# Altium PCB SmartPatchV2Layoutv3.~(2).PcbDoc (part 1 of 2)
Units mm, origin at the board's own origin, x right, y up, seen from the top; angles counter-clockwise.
Board outline 99.82 x 98.31 mm, 4 copper layers (Top Layer, Power, GroundPlane, Bottom Layer), stack 2.286 mm thick; 142 components, 77 nets, 387 pads, 123 vias.
Unrouted connection lines stored in the file: 2.
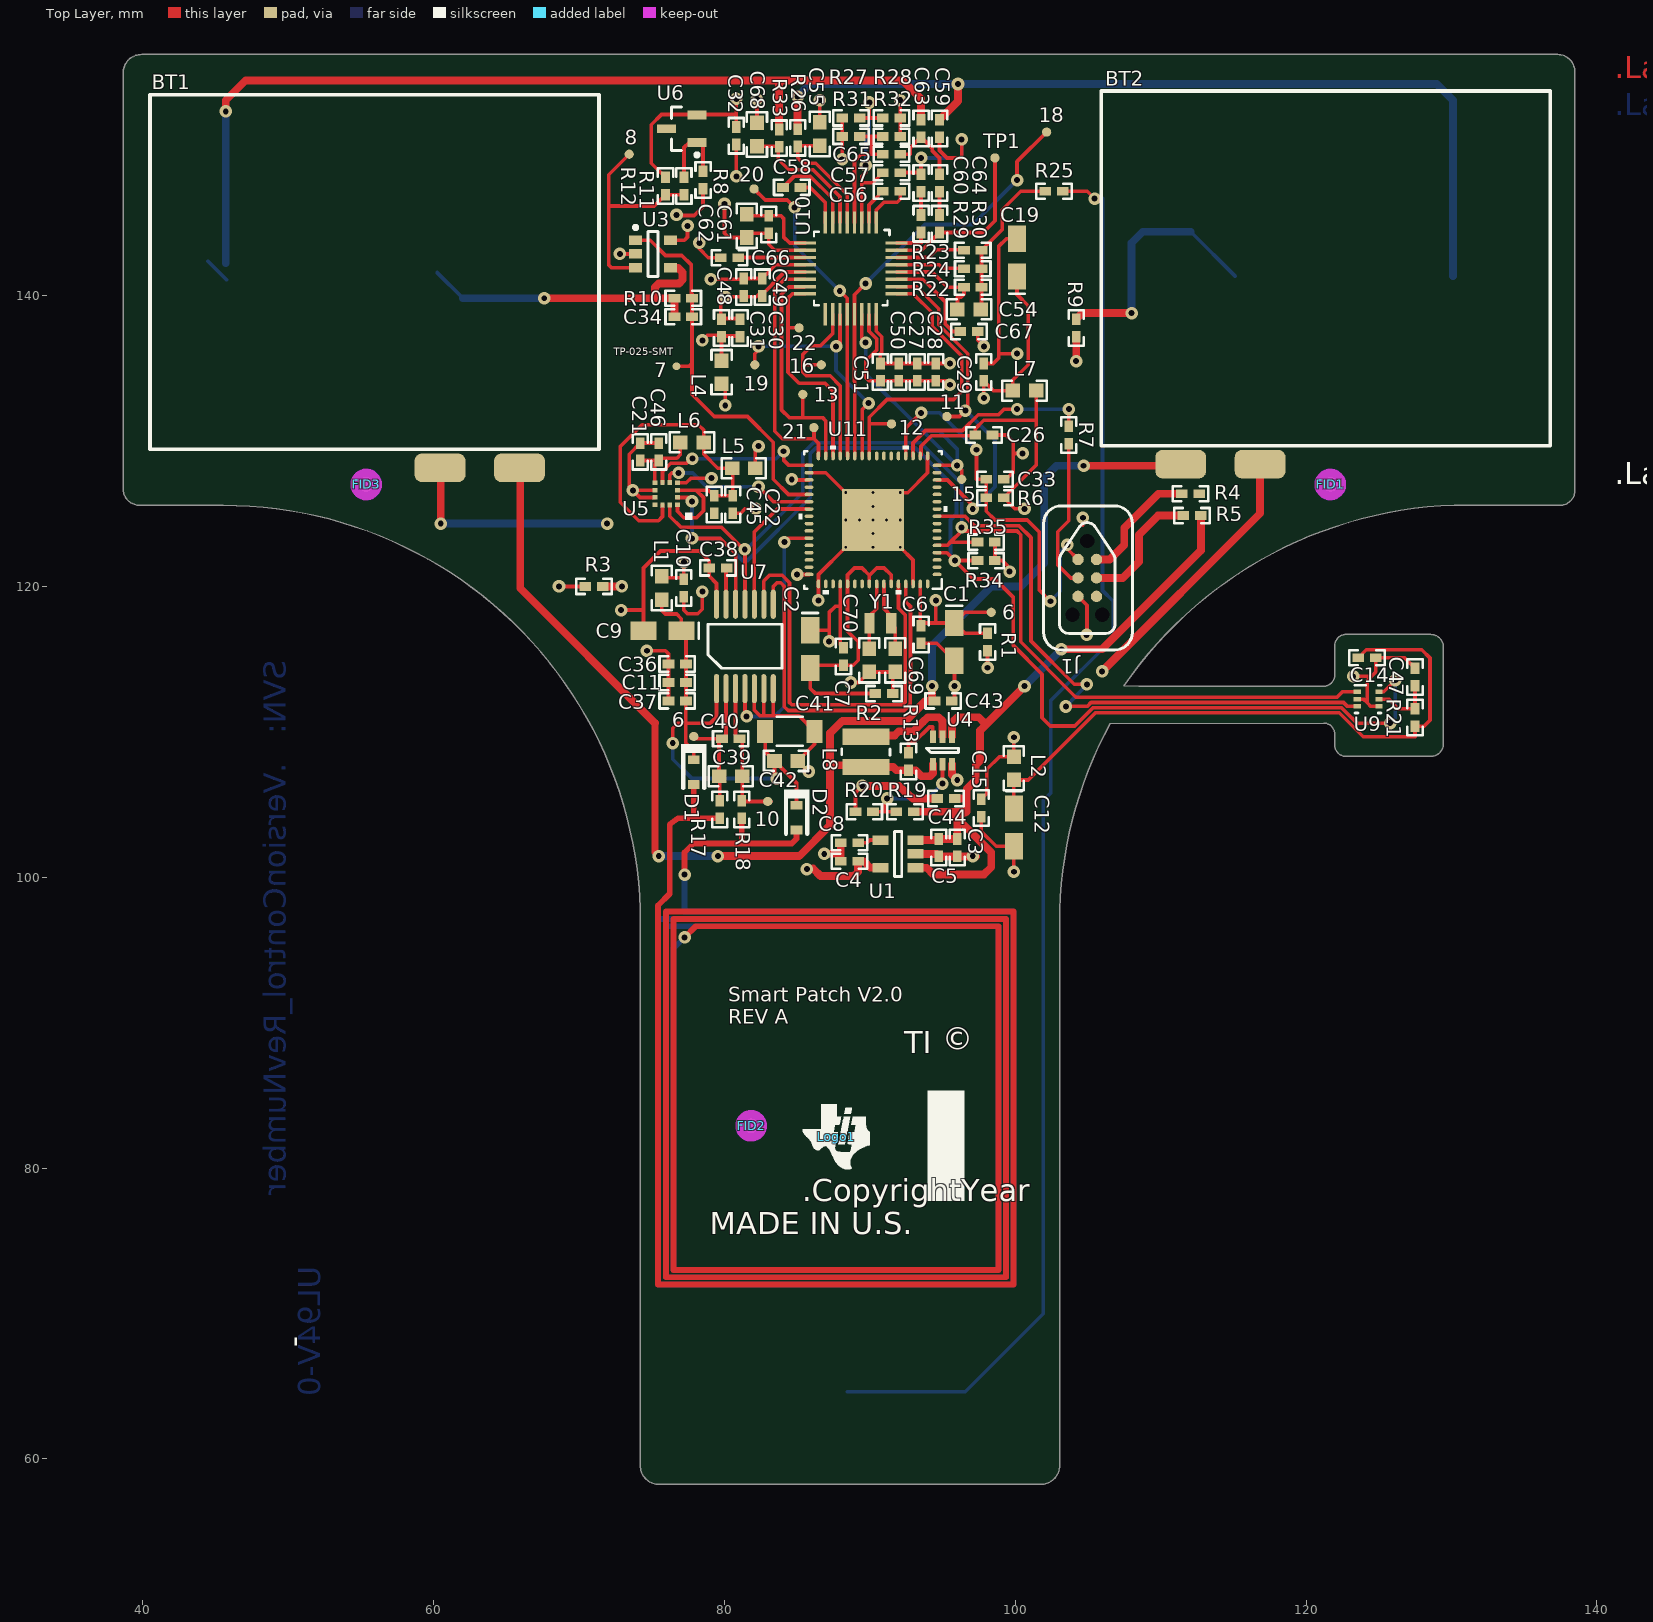
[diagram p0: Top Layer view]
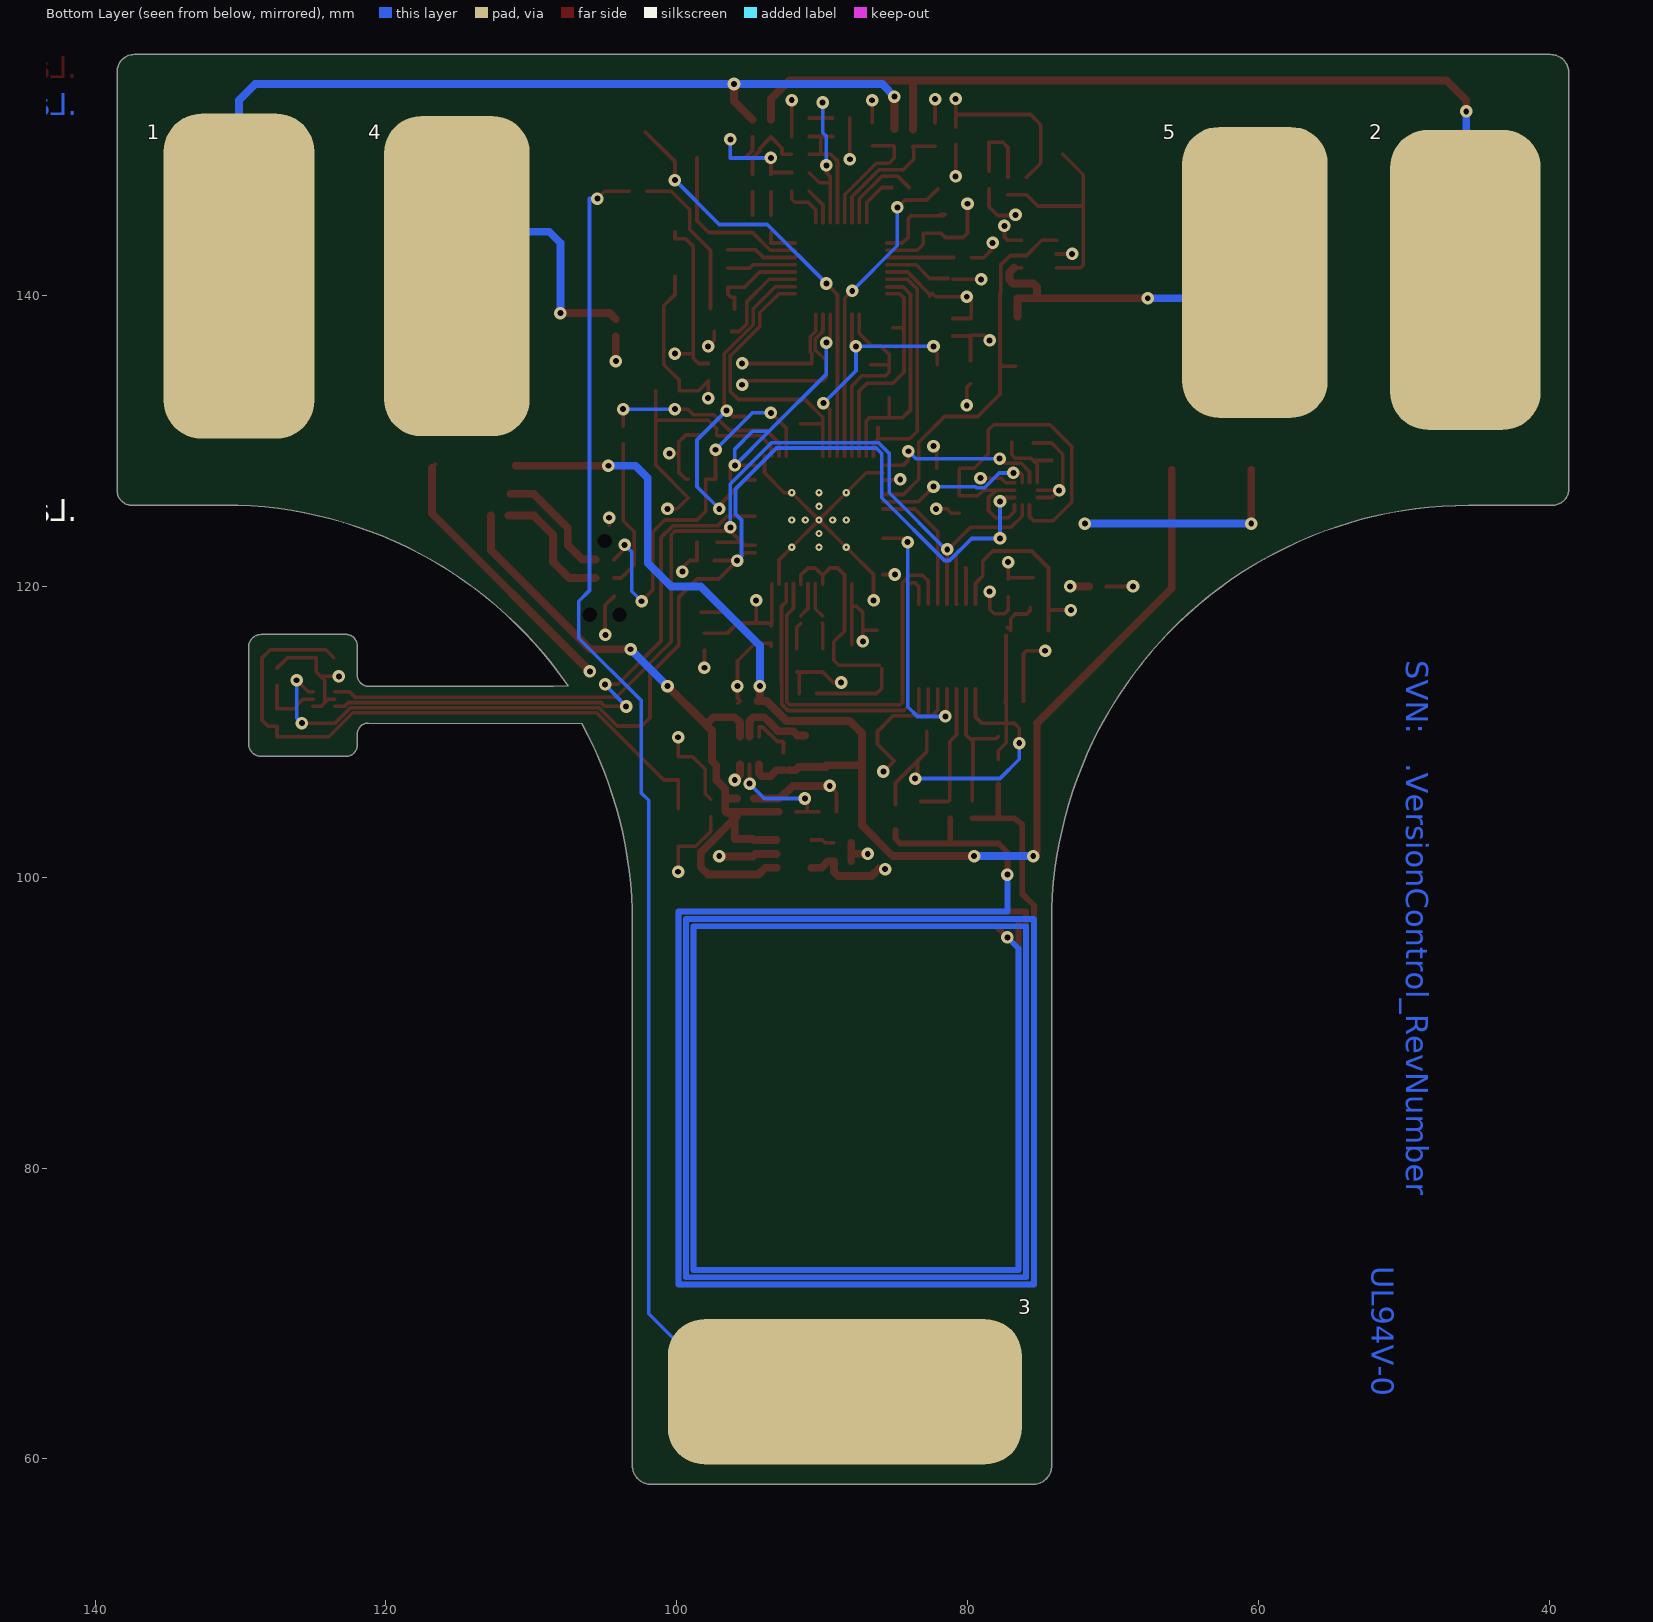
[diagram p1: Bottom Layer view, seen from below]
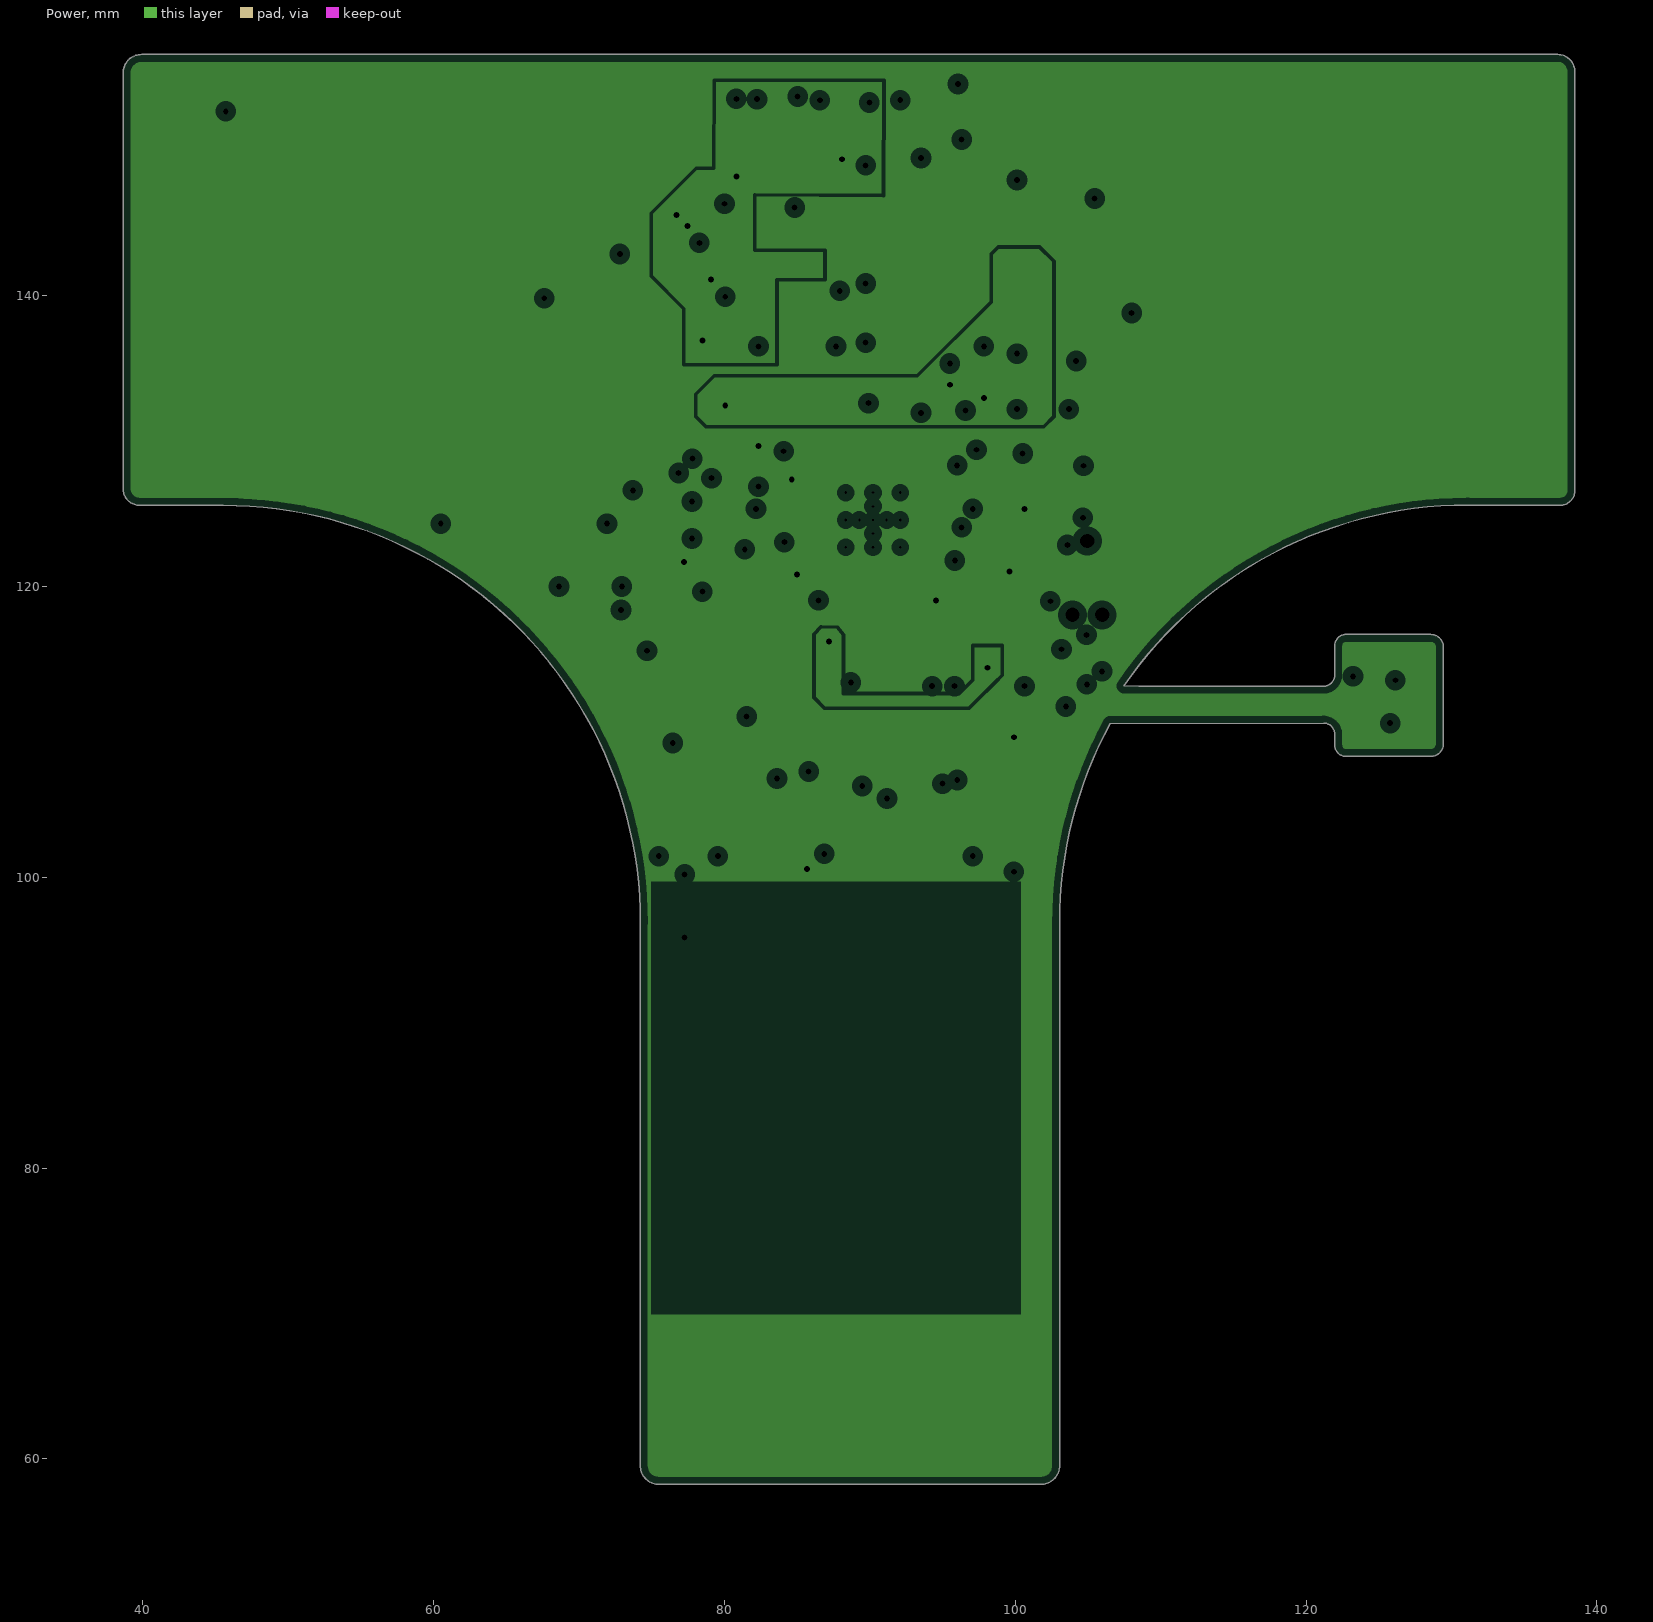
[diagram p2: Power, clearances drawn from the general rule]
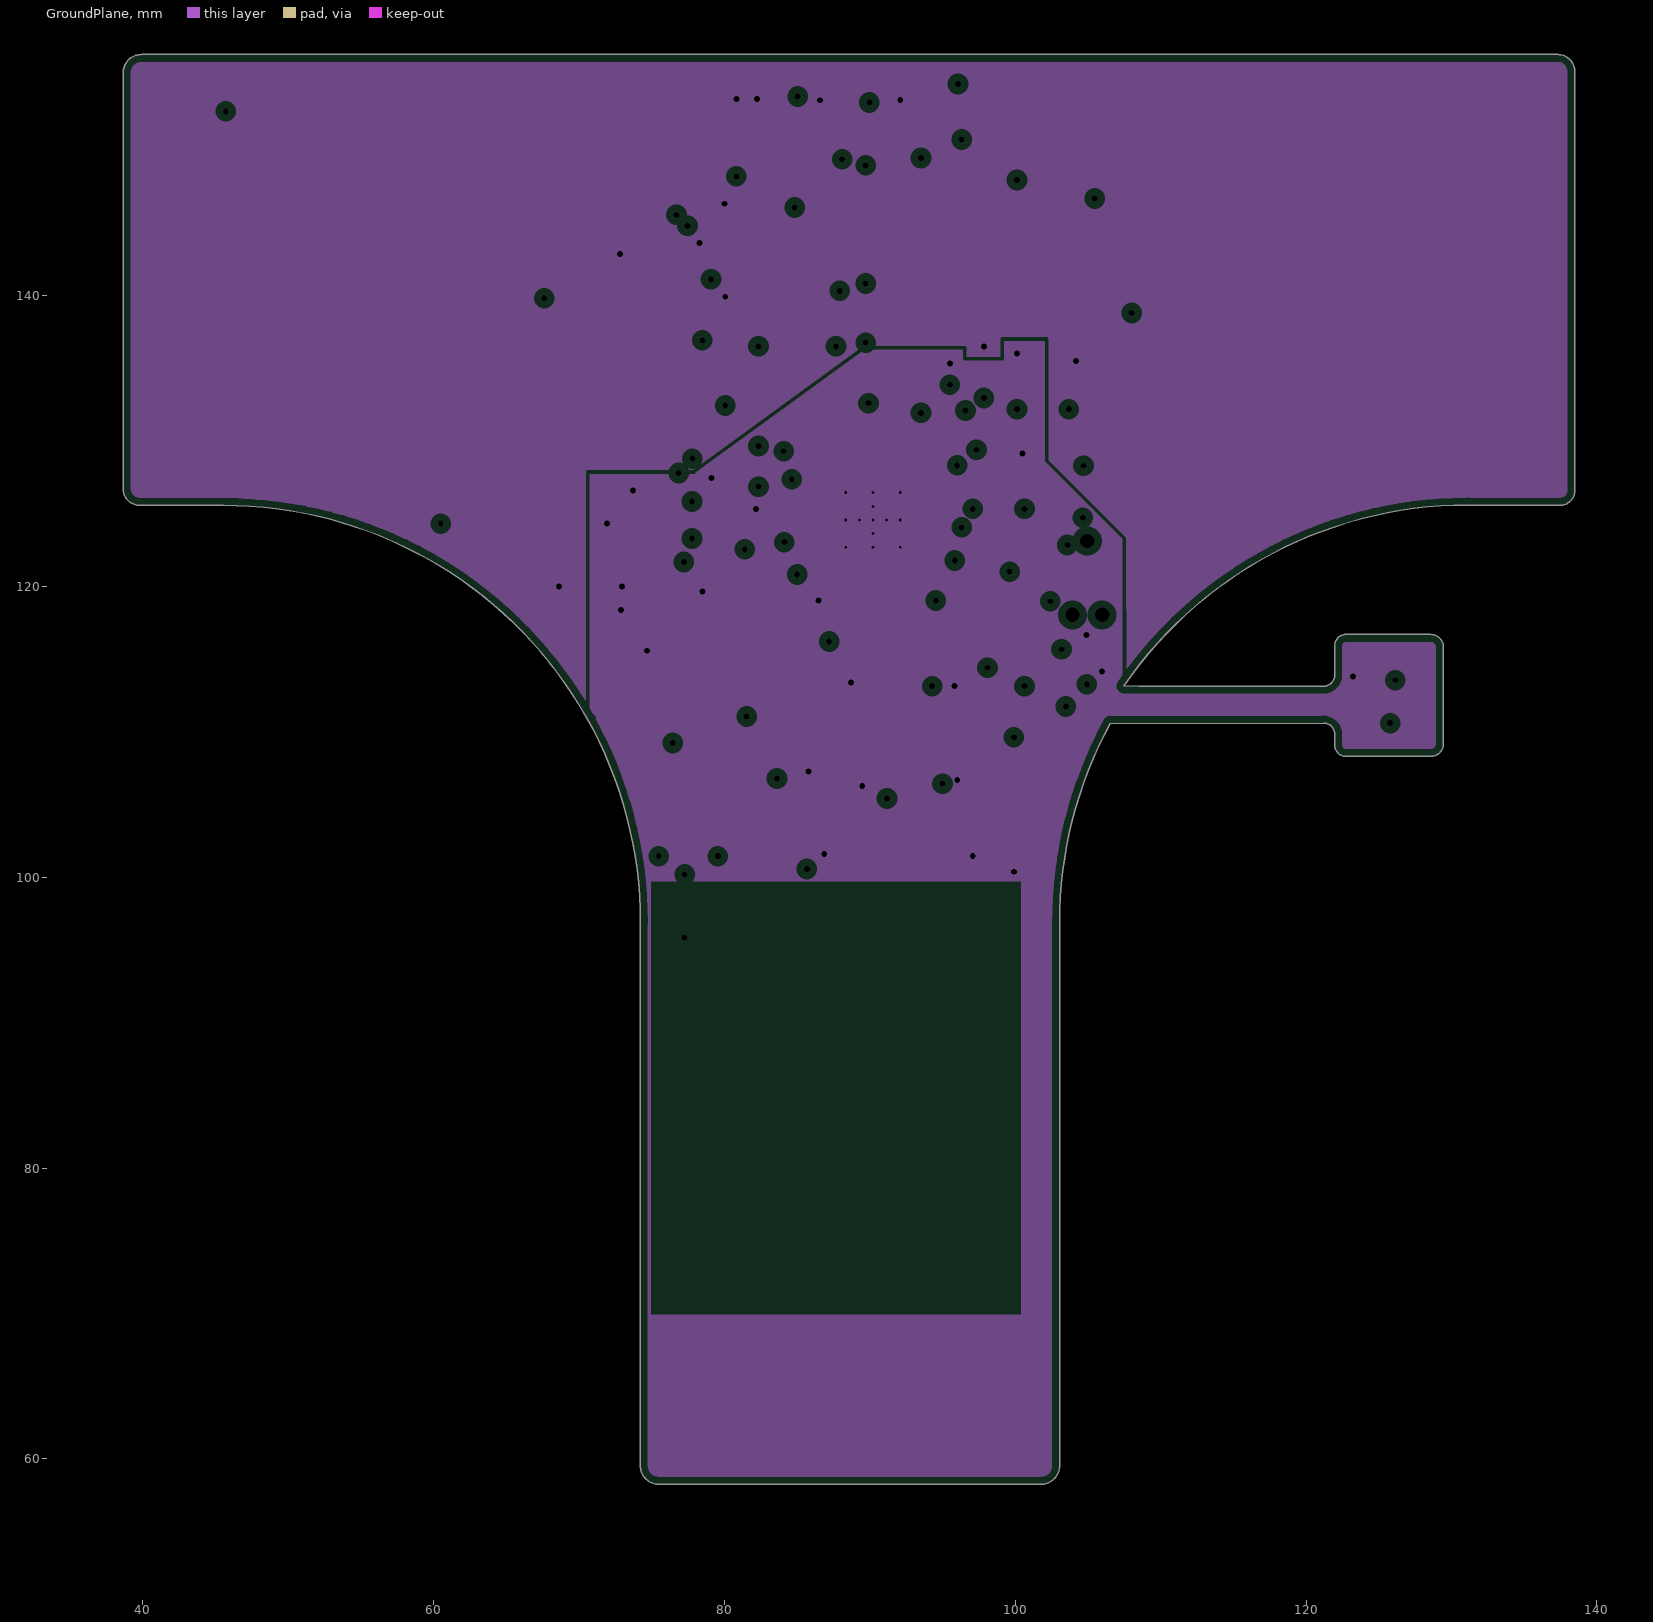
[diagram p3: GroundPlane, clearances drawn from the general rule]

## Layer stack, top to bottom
Top Layer: signal copper 0.0356
Dielectric: core 1.5037, FR-4, Dk 4.8
Power: plane copper 0.0356, net (Multiple Nets)
Dielectric: prepreg 0.32, FR-4, Dk 4.8
GroundPlane: plane copper 0.0356, net (Multiple Nets)
Dielectric: core 0.32, FR-4, Dk 4.8
Bottom Layer: signal copper 0.0356

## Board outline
74.219,59.527 ccw(c75.489,59.527) 75.489,58.257 101.778,58.257 ccw(c101.778,59.527) 103.048,59.527 103.048,96.875 cw(c131.74,96.875) 106.525,110.565 121.209,110.592 cw(c121.209,109.83) 121.971,109.83 121.971,109.068 ccw(c122.733,109.068) 122.733,108.306 128.575,108.306 ccw(c128.575,109.173) 129.442,109.173 129.442,115.82 ccw(c128.575,115.82) 128.575,116.688 122.733,116.688 ccw(c122.733,115.926) 121.971,115.926 121.971,113.894 cw(c121.209,113.894) 121.209,113.132 108.509,113.132 107.469,113.147 cw(c131.115,96.896) 131.115,125.588 132.639,125.576 137.454,125.567 ccw(c137.454,126.594) 138.481,126.594 138.481,155.379 ccw(c137.294,155.379) 137.294,156.566 39.929,156.566 ccw(c39.929,155.296) 38.659,155.296 38.659,126.714 38.657,126.714 ccw(c39.804,126.714) 39.804,125.568 45.537,125.568 cw(c45.537,96.876) 74.229,96.876 74.219,96.875

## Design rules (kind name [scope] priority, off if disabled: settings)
AcuteAngle [All] p1: minimum=4.50000000000000E+0001 checktracksonly=FALSE
AssemblyTestPointUsage [All] p1: valid=2
Clearance Clearance_BoardEdge_MountingHoles [OnCopper and InComponentClass('Mounting Holes') vs IsKeepOut] p1: gap=1.016
Clearance Clearance_BoardEdge_Poly [OnCopper and InPoly vs IsKeepOut] p2: gap=0.635
Clearance Clearance_BoardEdge [OnCopper and Not InComponentClass('Logo') and not InComponentClass('FiducialMark') and not InRegion(1000,500,4000,800) and Not IsKeepout vs IsKeepOut] p3: gap=1.905
Clearance Clearance_Poly [InPolygon] p4: gap=0.635
Clearance [All] p5: gap=0.1
ComponentClearance ComponentClearance_Shunt [InComponentClass('Header') vs InComponentClass('Shunt')] p1: gap=0 collisioncheckmode=3 verticalgap=0 showdistances=FALSE
ComponentClearance ComponentClearance_MountingHoles_FiducialMarks [InComponentClass('Mounting Holes') vs InComponentClass('FiducialMark')] p2: gap=1.27 collisioncheckmode=3 verticalgap=0.254 showdistances=FALSE
ComponentClearance ComponentClearance_Logo [InComponentClass('Logo')] p3: gap=1.27 collisioncheckmode=3 verticalgap=0.254 showdistances=FALSE
ComponentClearance ComponentClearance_ScrewToNut [(HasFootprint('NY PMS 440 0025 PH')) vs (HasFootprint('Keystone_1902C'))] p4: gap=0.127 collisioncheckmode=3 verticalgap=0.254 showdistances=FALSE
ComponentClearance ComponentClearance_MountingHoles [InComponentClass('Mounting Holes')] p5: gap=6.35 collisioncheckmode=3 verticalgap=2540 showdistances=FALSE
ComponentClearance ComponentClearance_SmallPassives [HasFootprint('0201*') or HasFootprint('0402*') or HasFootprint('0508') or HasFootprint('0603*') or HasFootprint('0612') or HasFootprint('0805*') or HasFootprint('0815*') or HasFootprint('0830*') or HasFootprint('1206*') or HasFootprint('1210*') or HasFootprint('1808*') or HasFootprint('1812*') or HasFootprint('1825*') or HasFootprint('2010*') or HasFootprint('2220*') or HasFootprint('2225*') or HasFootprint('2512*') or HasFootprint('2728*') or HasFootprint('3518*') vs HasFootprint('0201*') or HasFootprint('0402*') or HasFootprint('0508') or HasFootprint('0603*') or HasFootprint('0612') or HasFootprint('0805*') or HasFootprint('0815*') or HasFootprint('0830*') or HasFootprint('1206*') or HasFootprint('1210*') or HasFootprint('1808*') or HasFootprint('1812*') or HasFootprint('1825*') or HasFootprint('2010*') or HasFootprint('2220*') or HasFootprint('2225*') or HasFootprint('2512*') or HasFootprint('2728*') or HasFootprint('3518*')] p6: gap=0.508 collisioncheckmode=3 verticalgap=0.254 showdistances=FALSE
ComponentClearance ComponentClearance_THtoSMT [IsThruComponent vs IsSMTComponent] p7: gap=2.54 collisioncheckmode=3 verticalgap=0.762 showdistances=FALSE
ComponentClearance ComponentClearance_THtoTH [IsThruComponent vs IsThruComponent] p8: gap=3 collisioncheckmode=3 verticalgap=0.762 showdistances=FALSE
ComponentClearance [All] p9: gap=1.016 collisioncheckmode=3 verticalgap=0.254 showdistances=FALSE
DiffPairsRouting [All] p1: maxlimit=2.54 minlimit=0.254 mostfreqgap=0.254 maxuncoupledlength=25.4
FabricationTestPointUsage TestPointUsage [All] p1: valid=2 allowmultiple=FALSE
FabricationTestpoint Testpoint [All] p1: side=3 testpointundercomponent=TRUE minsize=1.016 maxsize=2.54 preferedsize=1.524 minholesize=0 maxholesize=1.016 preferedholesize=0.813 testpointgrid=0.025 allowsidetop=TRUE allowsidebottom=TRUE usegrid=TRUE gridtolerance=0
FanoutControl Fanout_LCC [IsLCC] p1: bgadir=Out bgaviamode=Centered fanoutstyle=Auto fanoutdirection=Alternating viagrid=0.025 // Fanout_LCC (Default Rule)
FanoutControl Fanout_BGA [IsBGA] p2: bgadir=Out bgaviamode=Centered fanoutstyle=Auto fanoutdirection=Alternating viagrid=0.025 // Fanout_BGA (Default Rule)
FanoutControl Fanout_Default [All] p4: bgadir=Out bgaviamode=Centered fanoutstyle=Auto fanoutdirection=Alternating viagrid=0.025 // Fanout_Default (Default Rule)
FanoutControl Fanout_Small [(CompPinCount < 5)] p5: bgadir=Out bgaviamode=Centered fanoutstyle=Auto fanoutdirection=OutThenIn viagrid=0.025 // Fanout_Small (Default Rule)
Height [All] p1: minheight=0 maxheight=55.4 prefheight=12.7
HoleSize [All] p1: absolutevalues=TRUE maxlimit=6.375 minlimit=0.1 maxpercent=80.000 minpercent=20.000
MinimumAnnularRing MinimumAnnularRing_ThermalPadVias [IsVia and InAnyComponent] p1: minimumring=0.15
MinimumAnnularRing [All] p2: minimumring=0.229
MinimumSolderMaskSliver MinimumSolderMaskSliver_Logo [InComponentClass('Logo') vs InComponentClass('Logo')] p1: minsoldermaskwidth=0.018
MinimumSolderMaskSliver [All] p2: minsoldermaskwidth=0.08
PlaneClearance [All] p1: clearance=0.508
PlaneConnect [All] p1: planeconnectstyle=Relief reliefexpansion=0.254 reliefentries=4 reliefconductorwidth=0.254 reliefairgap=0.254
PolygonConnect [All] p1: connectstyle=Relief reliefconductorwidth=0.254 reliefentries=4 polygonreliefangle="90 Angle" airgapwidth=0.254
RoomDefinition Transponder [InComponentClass('Transponder')] p1: confinementstyle=ConfineIn formatcopy=TRUE lockcomponents=FALSE outline 0,0 50.8,0 50.8,25.4 0,25.4
RoomDefinition Temperature [InComponentClass('Temperature')] p2: confinementstyle=ConfineIn formatcopy=TRUE lockcomponents=FALSE outline 0,0 50.8,0 50.8,25.4 0,25.4
RoomDefinition MSP430FR5XXX [InComponentClass('MSP430FR5XXX')] p3: confinementstyle=ConfineIn formatcopy=TRUE lockcomponents=FALSE outline 0,0 50.8,0 50.8,25.4 0,25.4
RoomDefinition "JTAG SPY-BY-WIRE" [InComponentClass('JTAG SPY-BY-WIRE')] p4: confinementstyle=ConfineIn formatcopy=TRUE lockcomponents=FALSE outline 0,0 50.8,0 50.8,25.4 0,25.4
RoomDefinition GSR [InComponentClass('GSR')] p5: confinementstyle=ConfineIn formatcopy=TRUE lockcomponents=FALSE outline 0,0 50.8,0 50.8,25.4 0,25.4
RoomDefinition ECG [InComponentClass('ECG')] p6: confinementstyle=ConfineIn formatcopy=TRUE lockcomponents=FALSE outline 0,0 50.8,0 50.8,25.4 0,25.4
RoomDefinition "Boost Converter" [InComponentClass('Boost Converter')] p7: confinementstyle=ConfineIn formatcopy=TRUE lockcomponents=FALSE outline 0,0 50.8,0 50.8,25.4 0,25.4
RoomDefinition BMA280 [InComponentClass('BMA280')] p8: confinementstyle=ConfineIn formatcopy=TRUE lockcomponents=FALSE outline 0,0 50.8,0 50.8,25.4 0,25.4
RoomDefinition Battery [InComponentClass('Battery')] p9: confinementstyle=ConfineIn formatcopy=TRUE lockcomponents=FALSE outline 0,0 50.8,0 50.8,25.4 0,25.4
RoutingVias ThermalPadVias [IsVia and InAnyComponent] p1: holewidth=0.2 width=0.5 viastyle="Through Hole" minholewidth=0.2 minwidth=0.5 maxholewidth=0.33 maxwidth=0.6
RoutingVias [All] p2: holewidth=0.406 width=0.864 viastyle="Through Hole" minholewidth=0.2 minwidth=0.66 maxholewidth=1.016 maxwidth=1.651
SMDToCorner [All] p1: distance=30000
SilkToSilkClearance SilkToSilkClearance_Pb-FreeLogo [(HasFootprint('Pb-Free_Overlay_Medium') OR HasFootprint('Pb-Free_Overlay_Small')) vs (HasFootprint('Pb-Free_Overlay_Medium') OR HasFootprint('Pb-Free_Overlay_Small'))] p1: silktosilkclearance=0
SilkToSilkClearance [All] p2: silktosilkclearance=0
SilkscreenOverComponentPads [IsPad] p1: minsilkscreentomaskgap=0.127
SolderMaskExpansion [All] p1: expansion=0.05
Width [All] p1: maxlimit=2.54 minlimit=0.152 preferedwidth=0.254 checkconnectedcopper=TRUE
12 further rules are at their usual default settings.

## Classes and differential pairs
component class Logo: Logo1
component class Designator: FID1 FID2 FID3 Logo1 ZZ1 ZZ2 ZZ3 ZZ4
component class FiducialMark: FID1 FID2 FID3
component class AssemblyNote: ZZ1 ZZ2 ZZ3 ZZ4
component class Battery: BT1 BT2 U?
component class BMA280: C45 C46 U5
component class "Boost Converter": C43 C44 L8 R13 R19 R20 U4
component class ECG: 11 12 13 15 16 18 19 20 21 22 C48 C49 C50 C51 C54 C55 C56 C57 C58 C59 C60 C61 C62 C63 C64 C65 C66 C67 C68 R22 R23 R24 R25 R26 R27 R28 R29 R30 R31 R32 R33 TP1 U10
component class GSR: 7 8 C34 R8 R9 R10 R11 R12 U3 U6
component class "JTAG SPY-BY-WIRE": C33 J1 R4 R5 R6 R7
component class MSP430FR5XXX: C69 C70 R34 R35 U11 Y1
component class "Power Filtering": 6 C1 C2 C3 C4 C5 C6 C7 C8 C9 C10 C11 C12 C14 C15 C19 C21 C22 C26 C27 C28 C29 C30 C31 C32 L1 L2 L4 L5 L6 L7 R1 R2 R3 U1
component class Temperature: C47 R21 U9
component class Transponder: 9 10 C36 C37 C38 C39 C40 C41 C42 D1 D2 R17 R18 U7

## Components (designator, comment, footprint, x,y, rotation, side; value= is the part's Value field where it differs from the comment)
1 "TP-025-SMT" TP_25MIL-SMT#1 130.099,141.326 r0 bottom
2 "TP-025-SMT" TP_25MIL-SMT#2 45.771,141.072 r0 bottom
3 "TP-025-SMT" TP_25MIL-SMT#3 88.443,64.618 r90 top
4 "TP-025-SMT" TP_25MIL-SMT#4 115.113,141.326 r270 bottom
5 "TP-025-SMT" TP_25MIL-SMT#5 60.249,141.58 r180 bottom
6 "TP-025-SMT" TP_25MIL-SMT#6 98.349,118.212 r90 top
7 "TP-025-SMT" TP_25MIL-SMT#7 76.708,135.128 r0 top
8 "TP-025-SMT" TP_25MIL-SMT#6 73.457,149.708 r0 top
9 "TP-025-SMT" TP_25MIL-SMT#6 77.897,109.676 r0 top
10 "TP-025-SMT" TP_25MIL-SMT#6 82.982,105.207 r270 top
11 "TP-025-SMT" TP_25MIL-SMT#6 95.301,131.674 r0 top
12 "TP-025-SMT" TP_25MIL-SMT#6 91.491,131.166 r0 top
13 "TP-025-SMT" TP_25MIL-SMT#6 85.395,133.198 r0 top
15 "TP-025-SMT" TP_25MIL-SMT#6 96.317,127.356 r0 top
16 "TP-025-SMT" TP_25MIL-SMT#6 86.665,135.23 r0 top
18 "TP-025-SMT" TP_25MIL-SMT#6 102.159,151.232 r0 top
19 "TP-025-SMT" TP_25MIL-SMT#6 82.093,135.23 r0 top
20 "TP-025-SMT" TP_25MIL-SMT#6 82.042,147.32 r0 top
21 "TP-025-SMT" TP_25MIL-SMT#6 86.157,130.912 r90 top
22 "TP-025-SMT" TP_25MIL-SMT#6 85.141,137.77 r0 top
BT1 "XXXXXX" Flat_Battery#1 63.246,128.27 r180 top
BT2 "XXXXXX" Flat_Battery#2 114.046,128.524 r0 top
C1 "293D106X9010A2TE3" 3216-18 95.809,116.18 r270 top
C2 "293D106X9010A2TE3" 3216-18 85.903,115.672 r270 top
C3 "C1005X5R0J105M" 0402 96.017,102.028 r270 top
C4 "C1005X5R1C225K050BC" 0402 88.6,101.092 r180 top
C5 "C1005X5R1A104K" 0402 94.747,102.028 r270 top
C6 "C1005X5R1A104K" 0402 93.523,116.688 r270 top
C7 "C1005X5R1A104K" 0402 88.189,115.164 r270 top
C8 "C1005X7R1E103K" 0402 88.6,102.362 r180 top
C9 "293D105X9016A2TE3" 3216-18 75.743,116.942 r180 top
C10 "C1005X5R1A104K" 0402 77.216,119.888 r270 top
C11 "C1005X5R1A104K" 0402 76.759,113.386 r180 top
C12 "293D106X9010A2TE3" 3216-18 99.906,103.422 r270 top
C14 "C1005X5R1A104K" 0402 124.183,115.089 r0 top
C15 "C1005X5R1A104K" 0402 97.665,104.75 r270 top
C19 "293D105X9016A2TE3" 3216-18 100.127,142.596 r90 top
C21 "CL05A106MQ5NUNC" 0402 74.219,129.247 r90 top
C22 "CL05A106MQ5NUNC" 0402 80.569,125.624 r270 top
C26 "C1005X5R1A104K" 0402 97.841,130.404 r0 top
C27 "C1005X5R1A104K" 0402 93.269,134.722 r90 top
C28 "C1005X5R1C225K050BC" 0402 94.539,134.722 r90 top
C29 "CL05A106MQ5NUNC" 0402 97.841,134.722 r90 top
C30 "CL05A106MQ5NUNC" 0402 81.077,137.77 r90 top
C31 "C1005X5R1A104K" 0402 79.807,137.77 r90 top
C32 "C1005X5R1A104K" 0402 80.823,150.978 r90 top
C33 "C1005X8R1H222K" 0402 98.603,127.356 r0 top
C34 "C1005X7R1E103K" 0402 77.175,138.532 r180 top
C36 "C1005X5R0J105M" 0402 76.759,114.656 r180 top
C37 "C1005X5R1A104K" 0402 76.759,112.116 r180 top
C38 "GRM155R60J474KE19D" 0402 79.553,121.26 r0 top
C39 "C1608C0G1H330J" 0603 80.437,106.941 r0 top
C40 "GRM1555C1H390JA01D" 0402 80.437,109.515 r0 top
C41 "C3216X5R1A107M160AC" 1206_190 84.501,110.023 r0 top
C42 "Used in BOM report" 0603 84.247,107.991 r0 top
C43 "CL05A106MQ5NUNC" 0402 95.047,112.116 r0 top
C44 "CL05A106MQ5NUNC" 0402 95.25,105.41 r180 top
C45 "C1005X5R1A104K" 0402 79.299,125.624 r270 top
C46 "C1005X5R1A104K" 0402 75.489,129.247 r90 top
C47 "C1005X7R1E103K" 0402 127.485,113.773 r90 top
C48 "C1005X5R1C105K050BC" 0402 81.331,140.564 r270 top
C49 "C1005X5R1A104K" 0402 82.601,140.564 r270 top
C50 "C1005X5R1C105K050BC" 0402 91.999,134.722 r90 top
C51 "C1005X5R1A104K" 0402 90.729,134.722 r90 top
C54 "C0603C152K5RACTU" 0603 96.825,139.04 r180 top
C55 "GRM1885C1H302JA01D" 0603 86.563,151.091 r90 top
C56 "GRM155R61A472KA01D" 0402 91.491,147.168 r0 top
C57 "C1005X8R1H222K" 0402 91.491,148.438 r0 top
C58 "GRM155R61A472KA01D" 0402 84.633,147.422 r180 top
C59 "C1005X5R1A104K" 0402 94.793,151.486 r270 top
C60 "C1005X8R1H222K" 0402 93.523,147.722 r90 top
C61 "C1005X5R1A104K" 0402 83.058,144.872 r270 top
C62 "C1608X5R0J106M" 0603 81.534,144.78 r270 top
C63 "C1005X5R1A104K" 0402 93.523,151.486 r270 top
C64 "C1005X8R1H222K" 0402 94.793,147.722 r90 top
C65 "C1005X8R1H222K" 0402 91.491,149.708 r0 top
C66 "C1005X5R1C105K050BC" 0402 80.361,142.596 r180 top
C67 "C1005X5R1C105K050BC" 0402 96.825,137.516 r0 top
C68 "GRM1885C1H302JA01D" 0603 82.241,151.063 r90 top
C69 "06035A100JAT2A" 0603 91.745,114.91 r270 top
C70 "06035A100JAT2A" 0603 89.967,114.91 r270 top
D1 "CDBU0130L" SOD-523F 77.897,107.229 r270 top
D2 "CDBU0130L" SOD-523F 84.963,104.089 r270 top
FID1 "Fiducial" Fiducial10-20 121.666,127 r0 top
FID2 "Fiducial" Fiducial10-20 81.839,82.906 r0 top
FID3 "Fiducial" Fiducial10-20 55.372,127 r90 top
J1 "TC2030-MCP-NL" TC2030-MCP-NL 104.953,120.574 r180 top
L1 "BLM18HG601SN1D" 0603 75.692,119.888 r270 top
L2 "BLM18HG601SN1D" 0603 99.906,107.486 r270 top
L4 "BLM18HG601SN1D" 0603 79.807,134.722 r90 top
L5 "BLM18HG601SN1D" 0603 81.331,128.118 r180 top
L6 "BLM18HG601SN1D" 0603 77.775,129.896 r0 top
L7 "BLM18HG601SN1D" 0603 100.635,133.452 r180 top
L8 "EPL3015-472MLB" EPL3015 89.738,108.61 r90 top
Logo1 "Texas Instruments" TI_Symbol_Overlay_Small 87.681,82.144 r0 top
R1 "ERJ-2GE0R00X" 0402 98.095,116.18 r270 top
R2 "ERJ-2GE0R00X" 0402 90.983,112.624 r180 top
R3 "ERJ-2GE0R00X" 0402 71.046,119.99 r180 top
R4 "ERJ-2GE0R00X" 0402 112.039,126.365 r0 top
R5 "ERJ-2GE0R00X" 0402 112.16,124.861 r0 top
R6 "CRCW040247K0JNED" 0402 98.603,126.086 r0 top
R7 "ERJ-2GE0R00X" 0402 103.683,130.404 r90 top
R8 "CRCW040221K5FKED" 0402 78.537,147.93 r270 top
R9 "CRCW040210K0FKED" 0402 104.191,137.77 r90 top
R10 "ERJ-2RKF1004X" 0402 77.175,139.802 r0 top
R11 "CRCW040211K8FKED" 0402 77.221,147.517 r90 top
R12 "CRCW04028K06FKED" 0402 75.951,147.517 r270 top
R13 "ERJ-2GE0R00X" 0402 92.659,107.95 r90 top
R17 "ERJ-2GE0R00X" 0402 79.675,104.655 r270 top
R18 "ERJ-2GE0R00X" 0402 81.199,104.655 r270 top
R19 "ERJ-2RKF1004X" 0402 92.415,104.496 r0 top
R20 "ERJ-2RKF2003X" 0402 89.621,104.496 r0 top
R21 "CRCW04024K99FKED" 0402 127.485,110.979 r270 top
R22 "ERJ-2RKF1004X" 0402 97.079,140.564 r0 top
R23 "ERJ-2GE0R00X" 0402 97.079,143.104 r0 top
R24 "ERJ-2RKF1003X" 0402 97.079,141.834 r0 top
R25 "ERJ-2RKF1003X" 0402 102.667,147.168 r0 top
R26 "CRCW040251K1FKED" 0402 85.039,150.837 r270 top
R27 "CRCW040210M0FKED" 0402 88.697,152.202 r180 top
R28 "CRCW040210M0FKED" 0402 91.491,152.202 r180 top
R29 "CRCW040240K2FKED" 0402 93.523,144.928 r270 top
R30 "CRCW040240K2FKED" 0402 94.793,144.928 r270 top
R31 "CRCW040210M0FKED" 0402 88.697,150.932 r180 top
R32 "CRCW040210M0FKED" 0402 91.491,150.932 r180 top
R33 "CRCW040251K1FKED" 0402 83.765,150.809 r270 top
R34 "CRCW04023K30JNED" 0402 98.003,121.768 r180 top
R35 "CRCW04023K30JNED" 0402 98.003,123.038 r180 top
TP1 "Pogo Pad" PogoPad 98.603,149.454 r0 top locked
U1 "TPS73030DBVR" DBV0005A_N 91.948,101.6 r180 top
U3 "LMP2231AMFE" MF05A_L 75.097,142.85 r0 top
U4 "TPS61220DCK" DCK0006A_N 94.996,108.712 r90 top
U5 "BMA280" LGA-12P 75.997,126.361 r90 top
U6 "LM4041AIM3-1.2" MF03A_N 77.064,151.46 r180 top
U7 "RF430CL331HCPW" PW0014A_M 81.414,115.864 r90 top
U9 "TMP112AIDRL" DRL0006A 124.257,112.243 r0 top
U10 "ADS1292RIPBS" PBS0032A_N 88.697,141.853 r270 top
U11 "MSP430FR5889IRGCR" RGC0064B 90.221,124.562 r180 top
Y1 "FC-12M 32.7680KA-A3" Epson_FC-12M 90.729,117.45 r0 top
ZZ1 "This Assembly Note is for PCB labels only" AssemblyNoteLabel 35.992,195.631 r0 top
ZZ2 "These assemblies are ESD sensitive, ESD precautions shall be observed." AssemblyNote 35.992,192.865 r0 top
ZZ3 "These assemblies must be clean and free from flux and all contaminants. Use of no clean flux is not acceptable." AssemblyNote 35.992,190.616 r0 top
ZZ4 "These assemblies must comply with workmanship standards IPC-A-610 Class 2, unless otherwise specified." AssemblyNote 35.992,188.366 r0 top

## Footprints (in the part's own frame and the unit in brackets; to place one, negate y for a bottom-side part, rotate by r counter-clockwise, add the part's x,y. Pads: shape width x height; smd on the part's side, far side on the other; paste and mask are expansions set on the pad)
0402 [mm] "0402 from SM-752 data"
  rect 0.8x0.6 smd: 1(-0.6,0) 2(0.6,0)
  silkscreen extent -1.22,-0.52 1.22,0.52, body extent -0.55,-0.3 0.55,0.3, height 0.6
0603 [mm] "0603 from SM-752 data"
  rect 1x0.95 smd: 1(-0.8,0) 2(0.8,0)
  silkscreen extent -1.52,-0.69 1.52,0.69, body extent -0.87,-0.47 0.87,0.47, height 0.85
1206_190 [mm] "1206_190"
  rect 1.1x1.6 smd: 1(-1.7,0) 2(1.7,0)
  silkscreen extent -0.9,-1 0.9,1, body extent -1.75,-0.95 1.75,0.95, height 1.9
3216-18 [mm] "Medium density IPC, based on Kemet T495 dimensions"
  rect 1.8x1.25 smd: 1(-1.3,0) 2(1.3,0)
  silkscreen extent -2.49,-0.54 -2.49,0.54, body extent -1.7,-0.9 1.7,0.9, height 1.8
AssemblyNote [mm] "Assembly Note"
AssemblyNoteLabel [mm] "Assembly Note for PCB Labels"
DBV0005A_N [mm] "SOT23, 5-Leads, Body 2.9x1.6mm, Pitch 0.95mm, Lead Span 2.8mm, IPC Medium Density"
  rect 1.1x0.65 smd: 1(-1.2,0.95) 2(-1.2,0) 3(-1.2,-0.95) 4(1.2,-0.95) 5(1.2,0.95)
  silkscreen extent -0.25,-1.55 0.25,1.55, body extent -1.42,-1.46 1.42,1.46, height 1.08
DCK0006A_N [mm] "SOT23, 6-Leads, Body 2x1.3mm, Pitch 0.65mm, Lead Span 2.1mm, IPC Medium Density"
  rect 0.85x0.4 smd: 1(-0.95,0.65) 2(-0.95,0) 3(-0.95,-0.65) 4(0.95,-0.65) 5(0.95,0) 6(0.95,0.65)
  silkscreen extent -0.15,-1.1 0.15,1.1, body extent -1.14,-1 1.14,1, height 0.94
DRL0006A [mm] "SOTFL, 6-Flat Leads, Body 1.2x1.6x0.6mm, Pitch 0.5mm, TI recommended"
  rect 0.5x0.3 smd: 1(-0.75,0.5) 2(-0.75,0) 3(-0.75,-0.5) 4(0.75,-0.5) 5(0.75,0) 6(0.75,0.5)
  silkscreen extent -0.9,-0.95 0.9,0.95, body extent -0.85,-0.85 0.85,0.85, height 0.62
EPL3015 [mm] "COILCRAFT"
  rect 1.12x3.2 smd: 1(-1.04,0) 2(1.04,0)
  silkscreen extent -0.22,-1.65 0.23,1.68, body extent -1.6,-1.6 1.6,1.6, height 1.55
Epson_FC-12M [mm] "Epson"
  rect 0.7x1.4 smd: 1(-0.75,0) 2(0.75,0)
  body extent -1.05,-0.63 1.05,0.63, height 0.6
Fiducial10-20 [mm]
  round 1 smd mask+0.5: 1(0,0)
  Top Layer keep-out circle w1.178: c0,0 r0.5
Flat_Battery#1 [mm]
  rrect50% 3.5x1.95 smd: 1(-2.667,0.127) 2(2.794,0.127)
  silkscreen extent -8.13,-25.53 22.73,-1.14, body extent -8.13,-25.53 22.73,-1.14, height 1
Flat_Battery#2 [mm]
  rrect50% 3.5x1.95 smd: 1(-2.667,-0.127) 2(2.794,-0.127)
  silkscreen extent -8.13,1.14 22.73,25.53, body extent -8.13,1.14 22.73,25.53, height 1
LGA-12P [mm]
  rect 0.3x0.35 smd mask+0.05: 1(-0.75,-0.775) 2(-0.25,-0.775) 3(0.25,-0.775) 4(0.75,-0.775) 7(0.75,0.775) 8(0.25,0.775) 9(-0.25,0.775) 10(-0.75,0.775)
  rect 0.35x0.3 smd mask+0.05: 5(0.775,-0.25) 6(0.775,0.25) 11(-0.775,0.25) 12(-0.775,-0.25)
  silkscreen extent -1.8,-1.8 -1.29,-1.3
MF03A_N [mm] "SOT23, 3-Leads, Body 2.9x1.3mm, Pitch 0.95mm, Lead Span 2.4mm, IPC Medium Density"
  rect 1.3x0.6 smd: 1(-1.05,0.95) 2(-1.05,-0.95) 3(1.05,0)
  silkscreen extent -1.18,-1.5 0.7,1.92, body extent -0.7,-1.5 0.7,1.5, height 1.12
MF05A_L [mm] "SOT23, 5-Leads, Body 2.9x1.6mm, Pitch 0.95mm, Lead Span 2.8mm, IPC High Density"
  rect 0.9x0.65 smd: 1(-1.2,0.95) 2(-1.2,0) 3(-1.2,-0.95) 4(1.2,-0.95) 5(1.2,0.95)
  silkscreen extent -1.32,-1.55 0.35,1.95, body extent -0.9,-1.55 0.9,1.55, height 1.19
PBS0032A_N [mil]
  rect 60x9 smd: 1(-124,68.9) 2(-124,49.21) 3(-124,29.53) 4(-124,9.84) 5(-124,-9.84) 6(-124,-29.53) 7(-124,-49.21) 8(-124,-68.9) 17(124,-68.9) 18(124,-49.21) 19(124,-29.53) 20(124,-9.84) 21(124,9.84) 22(124,29.53) 23(124,49.21) 24(124,68.9)
  rect 9x60 smd: 9(-68.9,-124) 10(-49.21,-124) 11(-29.53,-124) 12(-9.84,-124) 13(9.84,-124) 14(29.53,-124) 15(49.21,-124) 16(68.9,-124) 25(68.9,124) 26(49.21,124) 27(29.53,124) 28(9.84,124) 29(-9.84,124) 30(-29.53,124) 31(-49.21,124) 32(-68.9,124)
  silkscreen extent -104,-100 100,104, body extent -140,-140 140,140, height 48
PogoPad [mm] "No Solder Paste"
  round 0.635 smd paste-0.889: 1(0,0)
PW0014A_M [mm] "TSOP, 14-Leads, Body 5x4.4mm, Pitch 0.65mm, IPC Low Density"
  oval 2x0.35 smd: 1(-2.9,1.95) 2(-2.9,1.3) 3(-2.9,0.65) 4(-2.9,0) 5(-2.9,-0.65) 6(-2.9,-1.3) 7(-2.9,-1.95) 8(2.9,-1.95) 9(2.9,-1.3) 10(2.9,-0.65) 11(2.9,0) 12(2.9,0.65) 13(2.9,1.3) 14(2.9,1.95)
  silkscreen extent -1.5,-2.55 1.53,2.55, body extent -3.21,-2.5 3.21,2.5, height 0.98
RGC0064B [mm]
  oval 0.6x0.24 smd mask+0.07: 1(-4.4,3.75) 2(-4.4,3.25) 3(-4.4,2.75) 4(-4.4,2.25) 5(-4.4,1.75) 6(-4.4,1.25) 7(-4.4,0.75) 8(-4.4,0.25) 9(-4.4,-0.25) 10(-4.4,-0.75) 11(-4.4,-1.25) 12(-4.4,-1.75) 13(-4.4,-2.25) 14(-4.4,-2.75) 15(-4.4,-3.25) 16(-4.4,-3.75) 33(4.4,-3.75) 34(4.4,-3.25) 35(4.4,-2.75) 36(4.4,-2.25) 37(4.4,-1.75) 38(4.4,-1.25) 39(4.4,-0.75) 40(4.4,-0.25) 41(4.4,0.25) 42(4.4,0.75) 43(4.4,1.25) 44(4.4,1.75) 45(4.4,2.25) 46(4.4,2.75) 47(4.4,3.25) 48(4.4,3.75)
  oval 0.24x0.6 smd mask+0.07: 17(-3.751,-4.4) 18(-3.251,-4.4) 19(-2.751,-4.4) 20(-2.251,-4.4) 21(-1.75,-4.4) 22(-1.25,-4.4) 23(-0.75,-4.4) 24(-0.25,-4.4) 25(0.25,-4.4) 26(0.75,-4.4) 27(1.25,-4.4) 28(1.75,-4.4) 29(2.251,-4.4) 30(2.751,-4.4) 31(3.251,-4.4) 32(3.751,-4.4) 49(3.751,4.4) 50(3.251,4.4) 51(2.751,4.4) 52(2.251,4.4) 53(1.75,4.4) 54(1.25,4.4) 55(0.75,4.4) 56(0.25,4.4) 57(-0.25,4.4) 58(-0.75,4.4) 59(-1.25,4.4) 60(-1.75,4.4) 61(-2.251,4.4) 62(-2.751,4.4) 63(-3.251,4.4) 64(-3.751,4.4)
  rect 4.25x4.25 smd paste-2.112: 65(0,0)
  silkscreen extent -5.1,-5.1 5.1,5.1, body extent -4.57,-4.57 4.57,4.57, height 1.01
SOD-523F [mm] "COMCHIP"
  rect 0.6x0.8 smd paste-0.05: 1(-0.85,0) 2(0.85,0)
  silkscreen extent -1.92,-0.87 1.1,0.88, body extent -0.9,-0.5 0.9,0.5, height 0.85
TC2030-MCP-NL [mil] "TAG-CONNECT"
  round 31 smd paste-16: 1(-25,-50) 2(25,-50) 3(-25,0) 4(25,0) 5(-25,50) 6(25,50)
  round 25 hole 39 unplated: MH1(0,-100) MH2(-40,100) MH3(40,100)
  silkscreen extent -122,-195 118,195
TI_Symbol_Overlay_Small [mm]
  silkscreen extent -2.3,-2.23 2.3,2.24
TP_25MIL-SMT#1 [mm]
  rrect50% 10.35x22.35 smd mask-0.064: 1(0,0)
TP_25MIL-SMT#2 [mm]
  rrect50% 10.35x20.635 smd mask-0.064: 1(0,0)
TP_25MIL-SMT#3 [mm]
  rrect50% 10x24.35 smd far side mask-0.064: 1(0,0)
TP_25MIL-SMT#4 [mm]
  rrect50% 22x10 smd mask-0.064: 1(0,0)
TP_25MIL-SMT#5 [mm]
  rrect50% 10x20 smd mask-0.064: 1(0,0)
TP_25MIL-SMT#6 [mm]
  round 0.635 smd mask-0.064: 1(0,0)
TP_25MIL-SMT#7 [mm]
  round 0.535 smd mask-0.064: 1(0,0)

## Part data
1 2 3 4 5 6 7 8 9 10 11 12 13 15 16 18 19 20 21 22: "Test Point, O.025\""
BT1 BT2: library part Battery, "Battery, Lithium Polymer, 3V, 25mAh"
C1 C2 C12: "CAP, TA, 10 µF, 10 V, +/- 10%, 3.4 ohm, SMD"
C3 C36: "CAP, CERM, 1 µF, 6.3 V, +/- 20%, X5R, 0402"
C4 C28: "CAP, CERM, 2.2 µF, 16 V, +/- 10%, X5R, 0402"
C5 C6 C7 C10 C11 C14 C15 C26 C27 C31 C32 C37 C45 C46 C49 C51 C59 C61 C63: "CAP, CERM, 0.1 µF, 10 V, +/- 10%, X5R, 0402"
C8 C34 C47: "CAP, CERM, 0.01 µF, 25 V, +/- 10%, X7R, 0402"
C9 C19: "CAP, TA, 1 µF, 16 V, +/- 10%, 9.3 ohm, SMD"
C21 C22 C29 C30 C43 C44: "CAP, CERM, 10 µF, 6.3 V, +/- 20%, X5R, 0402"
C33 C57 C60 C64 C65: "CAP, CERM, 2200 pF, 50 V, +/- 10%, X8R, 0402"
C38: "CAP, CERM, 0.47 µF, 6.3 V, +/- 10%, X5R, 0402"
C39: "CAP, CERM, 33 pF, 50 V, +/- 5%, C0G/NP0, 0603"
C40: "CAP, CERM, 39pF, 50V, +/-5%, C0G/NP0, 0402"
C41: "CAP, CERM, 100 µF, 10 V, +/- 20%, X5R, 1206_190"
C42: library part Capacitor, "CAP, CERM, xxxF, xxV, [TempCo], xx%, [PackageReference]"
C48 C50 C66 C67: "CAP, CERM, 1 µF, 16 V, +/- 10%, X5R, 0402"
C54: "CAP, CERM, 1500 pF, 50 V, +/- 10%, X7R, 0603"
C55 C68: "CAP, CERM, 3000 pF, 50 V, +/- 5%, C0G/NP0, 0603"
C56 C58: "CAP, CERM, 4700 pF, 10 V, +/- 10%, X5R, 0402"
C62: "CAP, CERM, 10 µF, 6.3 V, +/- 20%, X5R, 0603"
C69 C70: "CAP, CERM, 10 pF, 50 V, +/- 5%, C0G/NP0, 0603"
D1 D2: "Diode, Schottky, 35V, 0.1A, SOD-523F"
FID1 FID2 FID3: "Fiducial mark.  There is nothing to buy or mount."
J1: "Footprint for TC2030-MCP-NL"
L1 L2 L4 L5 L6 L7: "Ferrite Bead, 600 ohm @ 100MHz, 0.2A, 0603"
L8: "Inductor, Shielded, Ferrite, 4.7uH, 1.2A, 0.14 ohm, SMD"
Logo1: library part TI_Logo, "Texas Instrument Corporate Signature"
R1 R2 R3 R4 R5 R7 R13 R17 R18 R23: "RES, 0, 5%, 0.063 W, 0402"
R6: "RES, 47 k, 5%, 0.063 W, 0402"
R8: "RES, 21.5 k, 1%, 0.063 W, 0402"
R9: "RES, 10.0 k, 1%, 0.063 W, 0402"
R10 R19 R22: "RES, 1.00 M, 1%, 0.1 W, 0402"
R11: "RES, 11.8 k, 1%, 0.063 W, 0402"
R12: "RES, 8.06 k, 1%, 0.063 W, 0402"
R20: "RES, 200 k, 1%, 0.1 W, 0402"
R21: "RES, 4.99 k, 1%, 0.063 W, 0402"
R24 R25: "RES, 100 k, 1%, 0.1 W, 0402"
R26 R33: "RES, 51.1 k, 1%, 0.063 W, 0402"
R27 R28 R31 R32: "RES, 10.0 M, 1%, 0.063 W, 0402"
R29 R30: "RES, 40.2 k, 1%, 0.063 W, 0402"
R34 R35: "RES, 3.3 k, 5%, 0.063 W, 0402"
TP1: library part PogoPad, "Pad for Pogo Pin Connector"
U1: "Single Output High PSRR LDO, 200 mA, Fixed 3 V Output, 2.7 to 5.5 V Input, 5-pin SOT-23 (DBV), -40 to 85 degC, Green (RoHS & no Sb/Br)"
U3: "Single Micropower Precision Op Amp"
U4: "LOW INPUT VOLTAGE STEP-UP CONVERTER IN 6 PIN SC-70 PACKAGE, DCK0006A"
U5: library part BMA250, "14 bit, digital, triaxial acceleration sensor with intelligent on-chip motion triggered interrupt controller"
U6: "Precision Micropower Shunt Voltage Reference, 3-pin SOT-23"
U7: library part RF430CL331H, "The Texas Instruments Dynamic NFC Interface Transponder RF430CL331H is an NFC Tag Type 4 device  that combines a wireless NFC interface and a wired SPI or I2C interface to connect the device to a host."
U9: "High-Accuracy, Low-Power, Digital Temperature Sensor With SMBus(TM)/Two-Wire Serial Interface, DRL0006A"
U10: "Low-Power, 2-Channel, 24-Bit Analog Front-End for Biopotential Measurement, PBS0032A"
U11: "Mixed-Signal Microcontrollers, RGC0064B"
Y1: "Crystal, 32.768kHz, 12.5pF, SMD"
ZZ1: library part AssemblyNoteLabel
ZZ2 ZZ3 ZZ4: library part AssemblyNote

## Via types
v1: diameter 0.864, hole 0.406, Top Layer to Bottom Layer, 110 vias
v2: diameter 0.5, hole 0.2, Top Layer to Bottom Layer, 13 vias

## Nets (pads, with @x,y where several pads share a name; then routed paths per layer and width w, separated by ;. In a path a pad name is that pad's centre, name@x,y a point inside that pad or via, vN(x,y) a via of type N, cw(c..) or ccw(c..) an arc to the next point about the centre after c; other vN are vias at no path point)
3V: C3.1 C5.1 C44.1 R4.2 R5.2 R19.2 U1.1 U1.3 U4.4 | length 52.1
  Top Layer w0.254: U1.3@93.148,102.55 U1.3@93.226,102.628 ; 94.386,100.178 94.488,100.178 ; C5.1@94.669,102.55 C5.1@94.747,102.628 ; 96.663,106.02 96.663,106.061 ; 112.758,123.591 112.76,123.593
  Top Layer w0.54: R19.2@93.015,104.496 96.663,104.496 ; U1.1@93.148,100.65 93.914,100.65 94.386,100.178 ; U1.3@93.148,102.55 C5.1@94.669,102.55 ; 94.488,100.178 97.841,100.178 98.349,100.686 98.349,101.702 95.901,104.15 96.663,104.496 ; C5.1@94.747,102.628 C3.1@96.017,102.628 96.017,104.034 ; U4.4@95.646,109.662 95.646,110.632 96.012,110.998 97.485,110.998 97.993,110.49 ; C44.1@95.85,105.41 96.663,105.41 ; 96.663,106.02 96.663,105.41 ; 96.663,106.061 97.282,106.68 97.282,107.696 97.587,108.001 97.587,110.084 97.993,110.49 ; v1(100.635,113.132) 97.993,110.49 ; v1(103.175,115.672) 105.969,115.672 112.76,122.463 112.76,123.591 ; 112.76,123.593 R5.2@112.76,124.861 ; 96.663,104.496 96.663,105.41
  Bottom Layer w0.54: v1(100.635,113.132) v1(103.175,115.672)
ADS1292_DRDY: 15.1 U10.22 U11.16 | length 19.6
  Top Layer w0.254: U10.22@89.447,138.704 89.447,137.039 89.713,136.773 v1(89.713,136.754) ; U11.16@94.621,128.312 v1(96.003,128.312) 96.317,127.998 15.1@96.317,127.356
  Bottom Layer w0.254: v1(89.713,136.754) 89.713,134.602 93.657,130.658 ; 93.657,130.658 v1(96.003,128.312) 96.003,129.448 94.793,130.658 93.657,130.658
ADS1292_ELA: 2.1 C63.1 R33.1 | length 66.6
  Top Layer w0.54: v1(45.72,152.654) 45.72,153.416 47.092,154.788 92.253,154.788 93.523,153.518 C63.1@93.523,152.086 ; R33.1@83.765,151.409 83.765,154.733
  Bottom Layer w0.254: 2.1@44.501,142.342 2.1@45.771,141.072
  Bottom Layer w0.54: 2.1@45.72,142.24 v1(45.72,152.654)
ADS1292_ERA: 1.1 C59.1 R26.1 | length 63.2
  Top Layer w0.54: R26.1@85.039,151.437 v1(85.039,153.67) ; C59.1@94.793,152.086 96.063,153.356 v1(96.063,154.534)
  Bottom Layer w0.54: v1(85.039,153.67) 85.852,154.534 v1(96.063,154.534) 128.981,154.534 130.099,153.416 1.1@130.099,141.326
ADS1292_GPIO1: 11.1 U10.26 U11.14 | length 24.5
  Top Layer w0.254: U10.26@91.846,140.603 93.229,140.603 94.744,139.089 94.744,137.976 96.728,135.992 ; U11.14@94.621,127.312 95.345,127.312 97.067,125.59 v1@97.067,125.336 ; 11.1@95.301,131.674 96.171,131.674 v1(96.578,132.08) 96.734,132.236 96.734,135.992
  Bottom Layer w0.254: v1(96.578,132.08) 98.603,130.055 98.603,126.848 v1(97.079,125.324)
ADS1292_GPIO2: 12.1 U10.25 U11.25 | length 20.5
  Top Layer w0.254: U11.25@89.971,128.962 89.971,129.729 ; 89.97,129.73 89.97,131.626 91.186,132.842 95.758,132.842 96.317,133.401 96.317,135.839 94.29,137.866 94.29,138.8 92.987,140.103 U10.25@91.846,140.103 ; 89.97,131.166 12.1@91.491,131.166
ADS1292_IN1N: C57.1 R27.1 R28.2 U10.3 | length 12.8
  Top Layer w0.254: R27.1@89.297,152.202 89.967,152.202 ; U10.3@89.447,145.003 89.447,148.184 89.713,148.45 v1(89.713,148.946) ; 89.522,147.753 90.206,147.753 C57.1@90.891,148.438 ; v1(89.967,153.264) 89.967,152.202 ; R28.2@90.891,152.202 89.967,152.202
  Bottom Layer w0.254: v1(89.713,148.946) 89.713,150.932 89.967,151.186 v1(89.967,153.264)
ADS1292_IN1P: C65.1 R31.1 R32.2 U10.4 | length 9.1
  Top Layer w0.254: U10.4@88.947,145.003 88.947,149.246 89.408,149.708 C65.1@90.891,149.708 ; R31.1@89.297,150.932 90.094,150.932 ; 90.094,149.835 90.094,150.932 ; R32.2@90.891,150.932 90.094,150.932
ADS1292_IN2N: C55.1 R26.2 U10.5 | length 8.7
  Top Layer w0.254: C55.1@86.563,150.291 85.093,150.291 R26.2@85.039,150.237 85.039,149.447 85.395,149.092 86.279,149.092 86.563,148.807 88.447,146.924 U10.5@88.447,145.003
ADS1292_IN2P: C68.1 R33.2 U10.6 | length 9.5
  Top Layer w0.254: C68.1@82.241,150.263 83.711,150.263 R33.2@83.765,150.209 ; R33.2@83.711,150.209 83.711,149.359 84.433,148.638 86.091,148.638 87.947,146.782 U10.6@87.947,145.003
ADS1292_MAIN_CLKSEL: 21.1 U10.14 U11.32 | length 17.1
  Top Layer w0.254: U10.14@85.547,141.103 84.137,141.103 83.471,140.437 83.471,130.658 83.979,130.15 86.157,130.15 ; 21.1@86.157,130.912 86.157,130.15 ; U11.32@86.47,128.962 86.47,129.837 86.157,130.15
ADS1292_RESET: 13.1 U10.15 U11.31 | length 16.9
  Top Layer w0.254: 13.1@85.395,132.944 85.395,131.597 ; U10.15@85.547,140.603 85.527,140.583 84.433,140.583 83.925,140.075 83.925,132.128 84.455,131.597 85.395,131.597 ; U11.31@86.97,128.962 86.97,131.368 86.741,131.597 85.395,131.597
ADS1292_RESP_MODP/IN3N: R29.2 U10.32 | length 2.4
  Top Layer w0.254: U10.32@91.846,143.603 93.514,143.603 93.523,143.612 R29.2@93.523,144.328
ADS1292_RESP_MODP/IN3P: R30.2 TP1.1 U10.31 | length 11.9
  Top Layer w0.254: U10.31@91.846,143.103 93.568,143.103 R30.2@94.793,144.328 97.795,144.328 98.603,145.136 TP1.1@98.603,149.454
ADS1292_RLD: 3.1 R25.2 | length 97.6
  Top Layer w0.254: R25.2@103.267,147.168 104.953,147.168 v1(105.461,146.66)
  Bottom Layer w0.254: 3.1@88.443,64.618 96.571,64.618 101.93,69.977 101.93,105.283 102.438,105.791 102.438,112.141 106.731,116.434 106.731,118.974 105.994,119.71 105.994,146.66 v1(105.461,146.66)
ADS1292_SPI_CS: 16.1 U10.18 U11.29 | length 14.1
  Top Layer w0.254: 85.487,135.23 16.1@86.665,135.23 ; 87.401,137.328 86.614,136.541 85.995,136.541 85.395,135.941 85.395,134.722 85.649,134.468 87.274,134.468 87.97,133.771 U11.29@87.97,128.962 ; 87.447,137.374 U10.18@87.447,138.704
ADS1292_SPI_DIN: 19.1 U10.19 U11.26 | length 17.3
  Top Layer w0.254: 19.1@82.093,135.23 82.093,135.992 82.347,136.246 v1(82.347,136.5) ; v1@87.947,136.766 U10.19@87.947,138.704 ; U11.26@89.471,128.962 89.471,132.143 v1(89.916,132.588)
  Bottom Layer w0.254: v1(82.347,136.5) v1(87.681,136.5) 87.681,134.823 v1(89.916,132.588)
ADS1292_SPI_DOUT: 18.1 U10.21 U11.27 | length 29.7
  Top Layer w0.254: U11.27@88.97,128.962 88.97,134.074 88.947,134.098 U10.21@88.947,138.704 88.947,140.052 v1(89.713,140.818) ; v1(100.127,147.93) 100.127,149.2 18.1@102.159,151.232
  Bottom Layer w0.254: v1(89.713,140.818) 93.777,144.882 97.079,144.882 v1(100.127,147.93)
ADS1292_SPI_SCLK: 20.1 U10.20 U11.28 | length 21.9
  Top Layer w0.254: 20.1@82.042,147.32 82.804,146.558 84.328,146.558 v1(84.836,146.05) ; v1(87.935,140.31) 88.443,139.802 88.443,133.96 88.47,133.932 U11.28@88.47,128.962
  Bottom Layer w0.254: v1(84.836,146.05) 84.836,143.408 v1(87.935,140.31)
ADS1292_START: 22.1 U10.16 U11.30 | length 15.2
  Top Layer w0.254: 84.379,137.77 22.1@85.141,137.77 ; U10.16@85.547,140.103 84.661,140.103 84.379,139.821 84.379,138.204 84.379,134.722 85.141,133.96 86.919,133.96 87.47,133.408 U11.30@87.47,128.962
ADS1292_VCAP1: C66.1 U10.11 | length 4.6
  Top Layer w0.254: C66.1@80.968,142.603 U10.11@85.547,142.603
ADS1292_VCAP2: C67.1 U10.27 | length 6.8
  Top Layer w0.254: U10.27@91.846,141.103 93.645,141.103 95.198,139.55 95.198,138.022 95.704,137.516 C67.1@96.225,137.516
ADS1292_VREFP: C61.1 C62.1 U10.9 | length 5.9
  Top Layer w0.254: C62.1@81.829,145.58 C62.1@81.534,145.58 81.642,145.472 C61.1@83.058,145.472 83.89,145.472 84.074,145.288 84.074,144.018 84.489,143.603 U10.9@85.547,143.603
ADS_AVCC: C30.1 C31.1 C32.1 C48.1 C49.1 L4.2 R8.2 R27.2 R31.2 U3.5 U10.12 | length 21.4
  Top Layer w0.254: U3.5@76.297,143.8 77.252,143.8 77.47,144.018 v1(77.47,144.78) ; v1(76.708,145.542) 76.757,145.493 77.929,145.493 78.537,146.101 R8.2@78.537,147.33 ; v1(78.486,136.906) 78.85,137.27 79.703,137.27 C31.1@79.761,137.212 ; v1(79.079,141.106) C48.1@81.031,141.106 ; L4.2@79.807,135.522 79.807,137.166 C31.1@79.761,137.212 ; v1(80.823,148.184) C32.1@80.823,150.378 ; C30.1@81.031,137.212 C31.1@79.761,137.212 ; C48.1@81.331,141.164 C49.1@82.601,141.164 83.54,142.103 U10.12@85.547,142.103 ; v1(88.097,149.362) R31.2@88.097,150.932 R27.2@88.097,152.202
ADS_AVSS: C30.2 C31.2 C32.2 C48.2 C49.2 C55.2 C61.2 C62.2 C66.2 C67.2 C68.2 R3.2 R9.1 R12.1 R28.1 R32.1 U3.2 U6.2 U10.10 U10.13 | length 43.8
  Top Layer w0.254: v1(68.631,119.99) R3.2@70.446,119.99 ; v1(72.811,142.85) U3.2@73.897,142.85 ; R12.1@75.951,148.117 74.981,149.088 74.981,151.74 75.677,152.436 78.929,152.436 80.757,152.436 ; v1@78.029,143.612 v1(78.283,143.612) 78.283,143.205 78.892,142.596 C66.2@79.761,142.596 ; v1(80.01,146.304) 80.01,144.272 80.302,143.98 C62.2@81.534,143.98 81.826,144.272 C61.2@83.058,144.272 83.058,143.51 83.464,143.104 84.074,143.104 U10.10@85.547,143.103 ; C32.2@80.823,151.578 v1(80.823,153.518) ; C30.2@81.031,138.412 79.761,138.412 79.761,139.906 81.031,139.906 82.197,139.906 C49.2@82.428,140.137 ; C68.2@82.241,151.863 v1(82.241,153.496) ; C49.2@82.601,139.964 82.601,140.068 83.894,141.362 ; 83.894,141.373 84.125,141.603 U10.13@85.547,141.603 ; C55.2@86.563,151.891 v1(86.563,153.416) ; R32.1@92.091,150.932 R28.1@92.091,152.202 v1(92.091,153.426) ; C67.2@97.425,137.516 97.425,136.916 v1(97.841,136.5)
  Top Layer w0.54: v1(104.191,135.484) R9.1@104.191,137.17
  other v1: 80.061,139.906
ADS_DVCC: C19.1 C27.1 C28.1 C29.1 C50.1 C51.1 L4.1 L7.2 U10.23 | length 24.5
  Top Layer w0.254: L4.1@79.807,133.922 80.061,133.668 v1(80.061,132.436) ; 89.713,135.484 89.713,134.376 89.967,134.122 C51.1@90.729,134.122 C50.1@91.999,134.122 C27.1@93.269,134.122 C28.1@94.539,134.122 ; 89.729,135.5 90.475,136.246 90.475,137.008 89.947,137.536 U10.23@89.947,138.704 ; C28.1@94.567,134.15 C28.1@94.539,134.122 ; v1(95.504,133.858) 95.504,133.896 95.278,134.122 C28.1@94.539,134.122 ; v1(97.841,132.944) C29.1@97.841,134.122 98.511,133.452 L7.2@99.835,133.452 99.835,134.176 100.889,135.23 100.889,139.294 100.127,140.056 C19.1@100.127,141.296
ANTENNA: D1.2 D2.2 R17.2 R18.2 | length 600.2
  Top Layer w0.4: v1(77.267,95.86) 78.029,96.622 98.857,96.622 98.857,73 76.505,73 76.505,97.13 99.365,97.13 99.365,72.492 75.997,72.492 75.997,97.638 99.873,97.638 99.873,71.984 75.438,71.984 75.438,98.044 76.251,98.857 76.251,103.631 76.806,104.055 77.897,104.055 ; v1(77.267,100.178) 77.267,101.702 77.876,102.311 84.633,102.311 84.963,102.641 D2.2@84.963,103.239 ; D1.2@77.897,106.379 77.897,104.055 ; R17.2@79.675,104.055 77.897,104.055 ; 81.199,102.311 R18.2@81.199,104.055
  Bottom Layer w0.4: 75.438,97.079 75.438,71.984 99.873,71.984 99.873,97.638 77.267,97.638 v1(77.267,100.178) ; 75.489,97.13 99.365,97.13 99.365,72.492 75.997,72.492 75.997,96.622 98.857,96.622 98.857,73 76.505,73 76.505,95.098 v1(77.267,95.86)
BMA_AVCC: C21.1 C46.1 L6.1 U5.7 | length 5.4
  Top Layer w0.254: C21.1@74.219,128.647 C46.1@75.489,128.647 ; U5.7@75.222,127.111 75.222,128.38 C46.1@75.489,128.647 ; L6.1@76.975,129.896 76.975,129.045 76.735,128.805 75.647,128.805 C46.1@75.489,128.647
BMA_DVCC: C22.1 C45.1 L5.2 L6.2 U5.1 U5.3 U5.11 | length 28.8
  Top Layer w0.254: U5.11@75.747,125.586 75.747,124.794 75.463,124.511 74.117,124.511 72.847,125.781 72.847,129.616 74.346,131.115 78.207,131.115 78.575,130.747 L6.2@78.575,129.896 78.575,129.096 79.553,128.118 L5.2@80.531,128.118 80.569,128.08 C22.1@80.569,126.224 C45.1@79.299,126.224 78.912,126.611 78.054,126.611 ; U5.1@76.772,125.611 76.772,125.158 77.216,124.714 78.08,124.714 78.562,125.197 78.562,126.103 78.054,126.611 ; U5.3@76.772,126.611 78.054,126.611
BMA_INT1: U5.5 U11.38 | length 11
  Top Layer w0.254: U5.5@76.247,127.136 76.247,127.657 76.382,127.792 v1(76.857,127.792) ; v1(82.347,126.848) 83.363,125.832 ; 83.383,125.812 U11.38@85.821,125.812
  Bottom Layer w0.254: v1(76.857,127.792) 77.826,127.792 78.844,126.774 79.39,126.774 79.464,126.848 v1(82.347,126.848)
BMA_INT2: U5.6 U11.33 | length 12.2
  Top Layer w0.254: U5.6@75.747,127.136 75.747,127.88 76.319,128.451 77.394,128.451 77.721,128.778 v1(77.8,128.778) ; v1(84.074,129.286) 84.074,128.676 84.439,128.312 U11.33@85.821,128.312
  Bottom Layer w0.254: v1(77.8,128.778) 83.566,128.778 v1(84.074,129.286)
